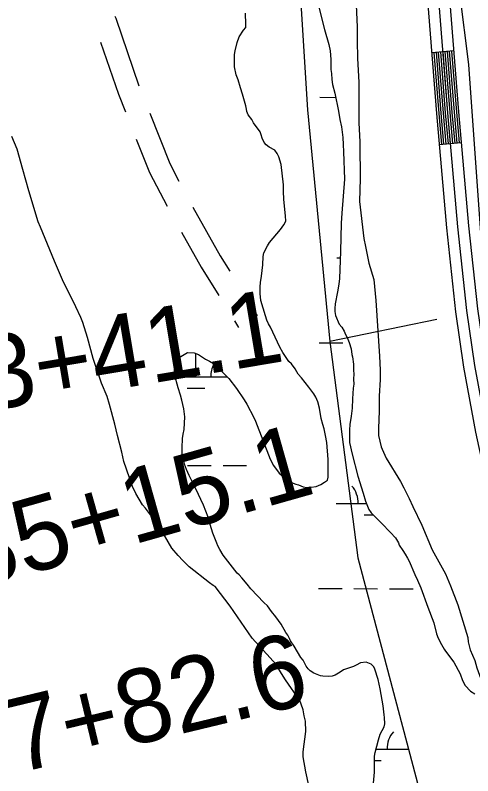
# Model space of a CAD drawing. Extents: x 3161665 to 3199565, y 885729 to 911164.
# Drawn here: x 3173076 to 3173696, y 899813 to 900843 of the extents above; entities that cross this region are included whole.
import ezdxf

# ---------------------------------------------------------------- set-up
doc = ezdxf.new("R2010")
doc.units = 0
for name, color, linetype in [('V-ROAD-CNTR', 7, 'Continuous'), ('V-SITE-VEGE', 7, 'Continuous'), ('V-SURV-IDEN', 7, 'Continuous'), ('V-TOPO-SHOR', 7, 'Continuous'), ('V-WETL-SWMP', 7, 'Continuous')]:
    doc.layers.add(name, color=color, linetype=linetype)

msp = doc.modelspace()

# ---------------------------------------------------------------- linework, layer by layer
at = {"layer": 'V-ROAD-CNTR'}
for p, q in [((3173670.6, 900794.3), (3173640.7, 900791.9)), ((3173680.8, 900669.8), (3173650.9, 900667.2)), ((3173388, 900462.1), (3173404.3, 900435.7)), ((3173373.3, 900428.8), (3173378.8, 900419.9))]:
    msp.add_line(p, q, dxfattribs=at)
for points in [[(3172866.1, 905009.4), (3173059.2, 904696.4), (3173271.3, 904357.4), (3173301.9, 904300.8), (3173323.1, 904255), (3173343.2, 904203.5), (3173359.2, 904153.1), (3173382.5, 904082.1), (3173390.1, 904052.4), (3173396.7, 903993.5), (3173420.3, 903725.8), (3173503.1, 902674.3), (3173566.1, 901884.6), (3173627.7, 901143), (3173662.2, 900710.5), (3173675.7, 900556.2), (3173688, 900442.9), (3173698.8, 900368.4), (3173714.8, 900280.9), (3173766.8, 900043), (3173909.7, 899439.9), (3174126.6, 898520.5), (3174367.6, 897523.3), (3174641.1, 896384.5)], [(3172853.2, 905001.7), (3173046.5, 904688.4), (3173258.3, 904349.8), (3173288.5, 904294), (3173309.3, 904249.1), (3173329, 904198.5), (3173344.9, 904148.5), (3173368.1, 904077.9), (3173375.3, 904049.7), (3173381.7, 903992), (3173405.4, 903724.5), (3173488.2, 902673.2), (3173551.1, 901883.4), (3173612.7, 901141.7), (3173647.3, 900709.3), (3173660.7, 900554.7), (3173673.1, 900441), (3173684, 900366), (3173700.1, 900277.9), (3173752.2, 900039.7), (3173895.1, 899436.4), (3174112, 898517), (3174353, 897519.8), (3174626.5, 896381.1)], [(3173330.7, 904274.3), (3173336.9, 904260.9), (3173357.3, 904208.5), (3173373.5, 904157.7), (3173396.9, 904086.3), (3173404.9, 904055.1), (3173411.6, 903995), (3173435.3, 903727), (3173518.1, 902675.5), (3173581, 901885.9), (3173642.6, 901144.2), (3173677.2, 900711.8), (3173690.6, 900557.6), (3173702.9, 900444.8), (3173713.6, 900370.9), (3173729.5, 900283.9), (3173781.5, 900046.4), (3173924.3, 899443.3), (3174141.2, 898524), (3174382.2, 897526.8), (3174655.7, 896387.9), (3174851.9, 895524.4), (3174955.2, 895029.6)], [(3173211.5, 900841.5), (3173212.5, 900838.7), (3173244, 900747)], [(3173192, 900806.1), (3173216.1, 900735.8), (3173225.6, 900711.9)], [(3173643.7, 900792.2), (3173650.3, 900709.5), (3173653.9, 900667.5)], [(3173646.7, 900792.4), (3173653.3, 900709.8), (3173656.9, 900667.8)], [(3173649.6, 900792.6), (3173656.2, 900710), (3173659.9, 900668)], [(3173652.6, 900792.9), (3173659.2, 900710.3), (3173662.9, 900668.3)], [(3173655.6, 900793.1), (3173662.2, 900710.5), (3173665.9, 900668.5)], [(3173658.6, 900793.4), (3173665.2, 900710.8), (3173668.9, 900668.8)], [(3173661.6, 900793.6), (3173668.2, 900711), (3173671.9, 900669.1)], [(3173664.6, 900793.8), (3173671.2, 900711.3), (3173674.8, 900669.3)], [(3173667.6, 900794.1), (3173674.2, 900711.5), (3173677.8, 900669.6)], [(3173258.7, 900709.8), (3173285.6, 900642), (3173298.1, 900617.9)], [(3173240.3, 900674.7), (3173258.2, 900629.5), (3173282, 900583.9)], [(3173316.9, 900582.7), (3173354.2, 900516.7), (3173367, 900496.1)], [(3173301.5, 900549), (3173328.4, 900501.4), (3173352.2, 900462.9)]]:
    msp.add_lwpolyline(points, dxfattribs=at)
at = {"layer": 'V-SITE-VEGE'}
for points in [[(3173538.2, 900856.6), (3173539.6, 900826.6), (3173539.6, 900808.5), (3173540.3, 900783.9), (3173541.8, 900751.8), (3173541.9, 900697.1), (3173543.3, 900671.1), (3173543.3, 900655), (3173544, 900634.4), (3173544, 900621.7), (3173542.8, 900590.3), (3173548.9, 900540.3), (3173550.9, 900529.6), (3173555.6, 900506.9), (3173562.4, 900484.9), (3173565.1, 900456.2), (3173569.9, 900380.8), (3173570.7, 900362.1), (3173570.7, 900349.4), (3173569.4, 900326.7), (3173569.4, 900306.7), (3173568.8, 900282.7), (3173568.8, 900273.3), (3173572.2, 900258), (3173573.6, 900254.7), (3173578.9, 900242.7), (3173598.3, 900211.3), (3173603, 900202.7), (3173610.4, 900188), (3173615.1, 900177.3), (3173627.2, 900152), (3173641.3, 900118.7), (3173659.4, 900086), (3173666.1, 900070), (3173676.1, 900044), (3173689.6, 900000), (3173690.3, 899994)], [(3173477.5, 899785), (3173470.1, 899817.7), (3173466.7, 899838.3), (3173466.7, 899845), (3173470, 899872.4), (3173469.9, 899886.4), (3173467.9, 899893.7), (3173466.6, 899901.7), (3173463.9, 899909.7), (3173461.9, 899914.4), (3173442.4, 899942.4), (3173437.1, 899951.1), (3173429.7, 899963.7), (3173421.7, 899972.4), (3173397.6, 899999), (3173367.5, 900042.3), (3173347.4, 900069), (3173344.7, 900070.3), (3173339.4, 900073.7), (3173312, 900095.6), (3173303.3, 900104.3), (3173297.2, 900110.9), (3173288.5, 900120.9), (3173271.8, 900149.6), (3173253, 900174.9), (3173249, 900179.6), (3173239.7, 900194.9), (3173235, 900204.2), (3173223.5, 900238.2), (3173220.8, 900250.9), (3173214.8, 900273.6), (3173211.4, 900288.9), (3173204, 900315.6), (3173200.7, 900326.3), (3173193.3, 900344.3), (3173181.9, 900377.6), (3173174.4, 900406.3), (3173167.7, 900426.3), (3173165, 900433), (3173158.3, 900447.7), (3173140.2, 900484.3), (3173129.5, 900509.7), (3173110.7, 900555.7), (3173107.4, 900563), (3173094.6, 900605), (3173086.5, 900633.7), (3173079.1, 900661.1), (3173071.7, 900678.4)], [(3173690.3, 899994), (3173693, 899983.3), (3173699, 899968.6), (3173701.7, 899958.6), (3173707.1, 899943.9), (3173719.1, 899913.9), (3173721.2, 899907.9), (3173726.5, 899895.3), (3173731.2, 899882.6), (3173735.9, 899865.9), (3173748.7, 899823.2), (3173760.1, 899786.5)]]:
    msp.add_lwpolyline(points, dxfattribs=at)
at = {"layer": 'V-TOPO-SHOR'}
msp.add_line((3173647.8, 900430.5), (3173502.6, 900400.5), dxfattribs=at)
for points in [[(3173363.3, 904242.9), (3173401, 904123.9), (3173426.9, 904006.5), (3173438.4, 903847.8), (3173467.1, 903467), (3173505, 903036.5), (3173511.5, 902920), (3173557.6, 902378), (3173597.8, 901857.1), (3173629.9, 901484.8), (3173641.3, 901329.5), (3173643.8, 901294.9), (3173678.3, 900872.8), (3173690.8, 900775.7), (3173712.9, 900465.8), (3173740.4, 900318.1), (3173758.8, 900226.9), (3173778.8, 900127.2), (3173796.5, 900112.8), (3173810.8, 900105.2), (3173815.9, 900101.8)], [(3173437.8, 901270), (3173472.6, 900714.6), (3173502.6, 900400.5), (3173540.7, 900107.9), (3173696.1, 899521.1), (3173813.2, 898842.7), (3173897.8, 898618.7), (3173944.3, 898383.5), (3174056.2, 898405.7), (3174317.5, 897120.3), (3174410.6, 896685.9), (3174403.7, 896621), (3174354.3, 896540.6), (3174320.5, 896435.4), (3174318.1, 896366), (3174329.1, 896301.1), (3174346.9, 896225), (3174364.6, 896157.8), (3174520.1, 895584.5)]]:
    msp.add_lwpolyline(points, dxfattribs=at)
at = {"layer": 'V-WETL-SWMP'}
for p, q in [((3173489.2, 900731.5), (3173510.6, 900731.4)), ((3173512, 900514.1), (3173516.7, 900514.1)), ((3173488.3, 900398.8), (3173520.3, 900398.7)), ((3173321.1, 900352.8), (3173321.2, 900384.2)), ((3173293.1, 900352.9), (3173363.4, 900352.7)), ((3173309.1, 900337.4), (3173333.1, 900337.4)), ((3173309.9, 900232.8), (3173341.9, 900232.7)), ((3173357.9, 900232.6), (3173389.9, 900232.6)), ((3173511.1, 900181.5), (3173552.3, 900181.4)), ((3173549.1, 900165.9), (3173561.5, 900165.9)), ((3173487.4, 900066.1), (3173519.4, 900066)), ((3173535.4, 900066), (3173567.4, 900065.9)), ((3173583.4, 900065.8), (3173615.4, 900065.8)), ((3173565.2, 899848.6), (3173610.2, 899848.5)), ((3173563.1, 899833.2), (3173572.1, 899833.2))]:
    msp.add_line(p, q, dxfattribs=at)
for points in [[(3173486.5, 900858.9), (3173495.5, 900823.3), (3173501.1, 900803.1), (3173502.9, 900794.2), (3173503.9, 900782.8), (3173504.2, 900769), (3173504.8, 900763.5), (3173505.5, 900755.5), (3173506.4, 900749), (3173509.5, 900737.1), (3173514.5, 900712.5), (3173516.3, 900701.5), (3173518.5, 900691.3), (3173520.4, 900677.2), (3173520.7, 900667.4), (3173521.3, 900657.6), (3173522.7, 900620.4), (3173519.1, 900574.6), (3173518.2, 900561.1), (3173517, 900522.7), (3173515.6, 900486.2), (3173514.7, 900478.5), (3173513.2, 900468), (3173510.1, 900451.8), (3173509.5, 900445.3), (3173509.5, 900441.3), (3173510.5, 900436.1), (3173515.1, 900424.1), (3173518.8, 900420.1), (3173522.2, 900414.6), (3173524, 900410.3), (3173526.2, 900406.3), (3173528.7, 900399.3), (3173531.5, 900391), (3173532.7, 900383), (3173533.3, 900379.9), (3173534.6, 900369.8), (3173534.6, 900361.5), (3173535.2, 900356.9), (3173534.9, 900349.8), (3173535.2, 900342.8), (3173534.3, 900337.6), (3173533.4, 900323.1), (3173532.9, 900310.2), (3173531.7, 900299.5), (3173529.8, 900288.4), (3173529.2, 900281), (3173529.3, 900264.1), (3173533, 900247.9), (3173540.7, 900218.4), (3173547.9, 900195.4), (3173551, 900184.6), (3173555.6, 900173), (3173558.7, 900168.7), (3173572.8, 900154.6), (3173585.1, 900142), (3173591.6, 900134.7), (3173595.6, 900127.9), (3173596.8, 900124.9), (3173601.8, 900117.8), (3173604.9, 900112.9), (3173607.9, 900107.1), (3173610.1, 900103.4), (3173617.8, 900085)], [(3173408.7, 900480.7), (3173409.9, 900489.3), (3173411.7, 900504.7), (3173412.3, 900516), (3173413.2, 900520.9), (3173418.1, 900530.2), (3173420.9, 900534.8), (3173435.9, 900552.6), (3173440.5, 900558.8), (3173442.9, 900563.7), (3173442.6, 900570.8), (3173440.4, 900592.9), (3173439.8, 900604.5), (3173439.7, 900612.8), (3173436.9, 900640.5), (3173433.5, 900650.9), (3173431.4, 900655.2), (3173428, 900659.8), (3173420.6, 900664.1), (3173416.3, 900667.1), (3173413.8, 900670.2), (3173411, 900676), (3173409.8, 900680.6), (3173408.3, 900684.6), (3173399.3, 900696.9), (3173396.9, 900701.2), (3173392.2, 900707.6), (3173390.1, 900712.2), (3173389.8, 900715.6), (3173388.8, 900719.9), (3173384.2, 900735.6), (3173381.4, 900744.2), (3173378.3, 900754.9), (3173375.8, 900761.7), (3173373.4, 900772.7), (3173373.6, 900789.6), (3173374.5, 900794.5), (3173377.3, 900805.9), (3173380, 900813.3), (3173385.5, 900822.2), (3173388.9, 900825.9), (3173388.9, 900830.5), (3173388.2, 900845.5)], [(3173449.4, 899995.2), (3173448.2, 899998.3), (3173445.7, 900002.9), (3173443.2, 900006.6), (3173436.5, 900017.9), (3173429.7, 900027.7), (3173423.8, 900034.8), (3173418, 900042.5), (3173413.1, 900047.4), (3173395.5, 900065.8), (3173390.6, 900072.2), (3173383.5, 900080.8), (3173379.8, 900084.5), (3173377, 900086.9), (3173357.9, 900111.4), (3173353.6, 900118.8), (3173350.8, 900124), (3173349.3, 900127.7), (3173344, 900141.2), (3173340.3, 900152.9), (3173337.6, 900162.7), (3173331.4, 900179.2), (3173321.2, 900201.3), (3173311.9, 900219.1), (3173308.2, 900227.4), (3173305.5, 900234.5), (3173302.7, 900248.9), (3173302.6, 900256.6), (3173303.2, 900269.5), (3173304.1, 900275.3), (3173305.3, 900281.5), (3173306.2, 900298.7), (3173304.7, 900309.7), (3173301.9, 900321.1), (3173300.3, 900328.1), (3173297.2, 900338), (3173292.3, 900355.8), (3173292.3, 900363.7), (3173292.9, 900368.7), (3173295.3, 900374.5), (3173300.8, 900380.3), (3173309.7, 900385.6), (3173318.6, 900385.3), (3173324.5, 900382.9), (3173334.3, 900377), (3173339.8, 900374), (3173344.8, 900370.9), (3173347.2, 900368.2), (3173353.4, 900363), (3173365.7, 900350.4), (3173376.2, 900337.2), (3173386.6, 900321.6), (3173390, 900315.7), (3173399.6, 900297.9), (3173402.1, 900292.7), (3173421.8, 900241.5), (3173426.5, 900232.6), (3173433.9, 900222.5), (3173439.4, 900217.9), (3173442.5, 900215.7), (3173447.4, 900211.8), (3173450.8, 900209.9), (3173456.6, 900207.5), (3173460, 900206.6), (3173466.5, 900203.8), (3173471.4, 900202.9), (3173477.5, 900203.2), (3173484, 900204.2), (3173490.4, 900207.2), (3173495.6, 900210.3), (3173499.3, 900212.8), (3173500.2, 900217.1), (3173500.5, 900226.6), (3173500.5, 900241), (3173498.6, 900263.8), (3173497, 900273.6), (3173494.8, 900282.5), (3173493, 900288.3), (3173491.1, 900296.3), (3173488.6, 900310.4), (3173486.5, 900319), (3173483.7, 900325.2), (3173480.9, 900329.8), (3173474.1, 900339), (3173464.3, 900351.5), (3173459.7, 900356.4), (3173458.1, 900359.5), (3173455.7, 900363.8), (3173450.7, 900370.5), (3173447.3, 900373.6), (3173442.4, 900380.4), (3173439, 900385.6), (3173435, 900392.9), (3173422.1, 900420.2), (3173419.6, 900424.5), (3173417.4, 900429.7), (3173415.3, 900435.6), (3173409.1, 900456.1), (3173408.1, 900465.7), (3173408.1, 900474.9), (3173408.7, 900480.7)], [(3173617.8, 900085), (3173621.5, 900077.3), (3173626.2, 900067.2), (3173635.4, 900040.8), (3173643.5, 900019.6), (3173647.2, 900004.9), (3173649.6, 899999.1), (3173654, 899990.2), (3173657.7, 899984), (3173659.5, 899981.3), (3173670.6, 899966.2), (3173679.2, 899950.6), (3173682.6, 899941.7), (3173686.3, 899935), (3173693.4, 899927), (3173699.3, 899923.3)], [(3173561.9, 899802.6), (3173563.1, 899817.4), (3173563.1, 899838.9), (3173564, 899844.1), (3173568.6, 899861.3), (3173571, 899868.7), (3173576.5, 899878.8), (3173577.1, 899882.8), (3173576.8, 899891.4), (3173576.5, 899895.1), (3173574.9, 899907.1), (3173570.9, 899930.1), (3173568.1, 899942.7), (3173563.7, 899957.1), (3173562.2, 899960.2), (3173558.5, 899963.5), (3173552.1, 899966.3), (3173544.4, 899965.7), (3173538.5, 899962.3), (3173534.6, 899960.4), (3173521.4, 899956.1), (3173516.8, 899953), (3173509.7, 899948.7), (3173505.7, 899947.4), (3173501.4, 899947.1), (3173493.1, 899947.4), (3173490.1, 899948), (3173481.1, 899951.7), (3173475.9, 899954.8), (3173473.1, 899957.5), (3173470.7, 899960.9), (3173466.4, 899968.9), (3173463.3, 899972.5), (3173454.3, 899987.9), (3173449.4, 899995.2)]]:
    msp.add_lwpolyline(points, dxfattribs=at)
for centre, start, end in [((3173265.9, 900353.4), 359.0698, 34.608), ((3173376.4, 900353.1), 151.1756, 180.6135), ((3173505.9, 900182), 359.0698, 40.6135), ((3173615.4, 899849), 139.0698, 180.6135)]:
    msp.add_arc(centre, 35.2, start, end, dxfattribs=at)

# ---------------------------------------------------------------- texts
at = {"layer": 'V-SURV-IDEN'}
for s, rotation, p in [('283+41.1', 9.5269, (3172889.9, 900281.6)), ('285+15.1', 15.7931, (3172945.6, 900043.2)), ('287+82.6', 13.5272, (3172933, 899780.5))]:
    msp.add_text(s, height=100, rotation=rotation, dxfattribs=at).set_placement(p)

doc.saveas('drawing.dxf')
